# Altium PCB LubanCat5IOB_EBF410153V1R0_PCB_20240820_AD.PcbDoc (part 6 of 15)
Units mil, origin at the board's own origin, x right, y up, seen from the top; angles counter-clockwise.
Board outline 6811.02 x 4055.12 mil, 6 copper layers (TOP, GND02, ART03, ART04, PWR05, BOTTOM), stack 59.279 mil thick; 981 components, 783 nets, 3627 pads, 2669 vias.
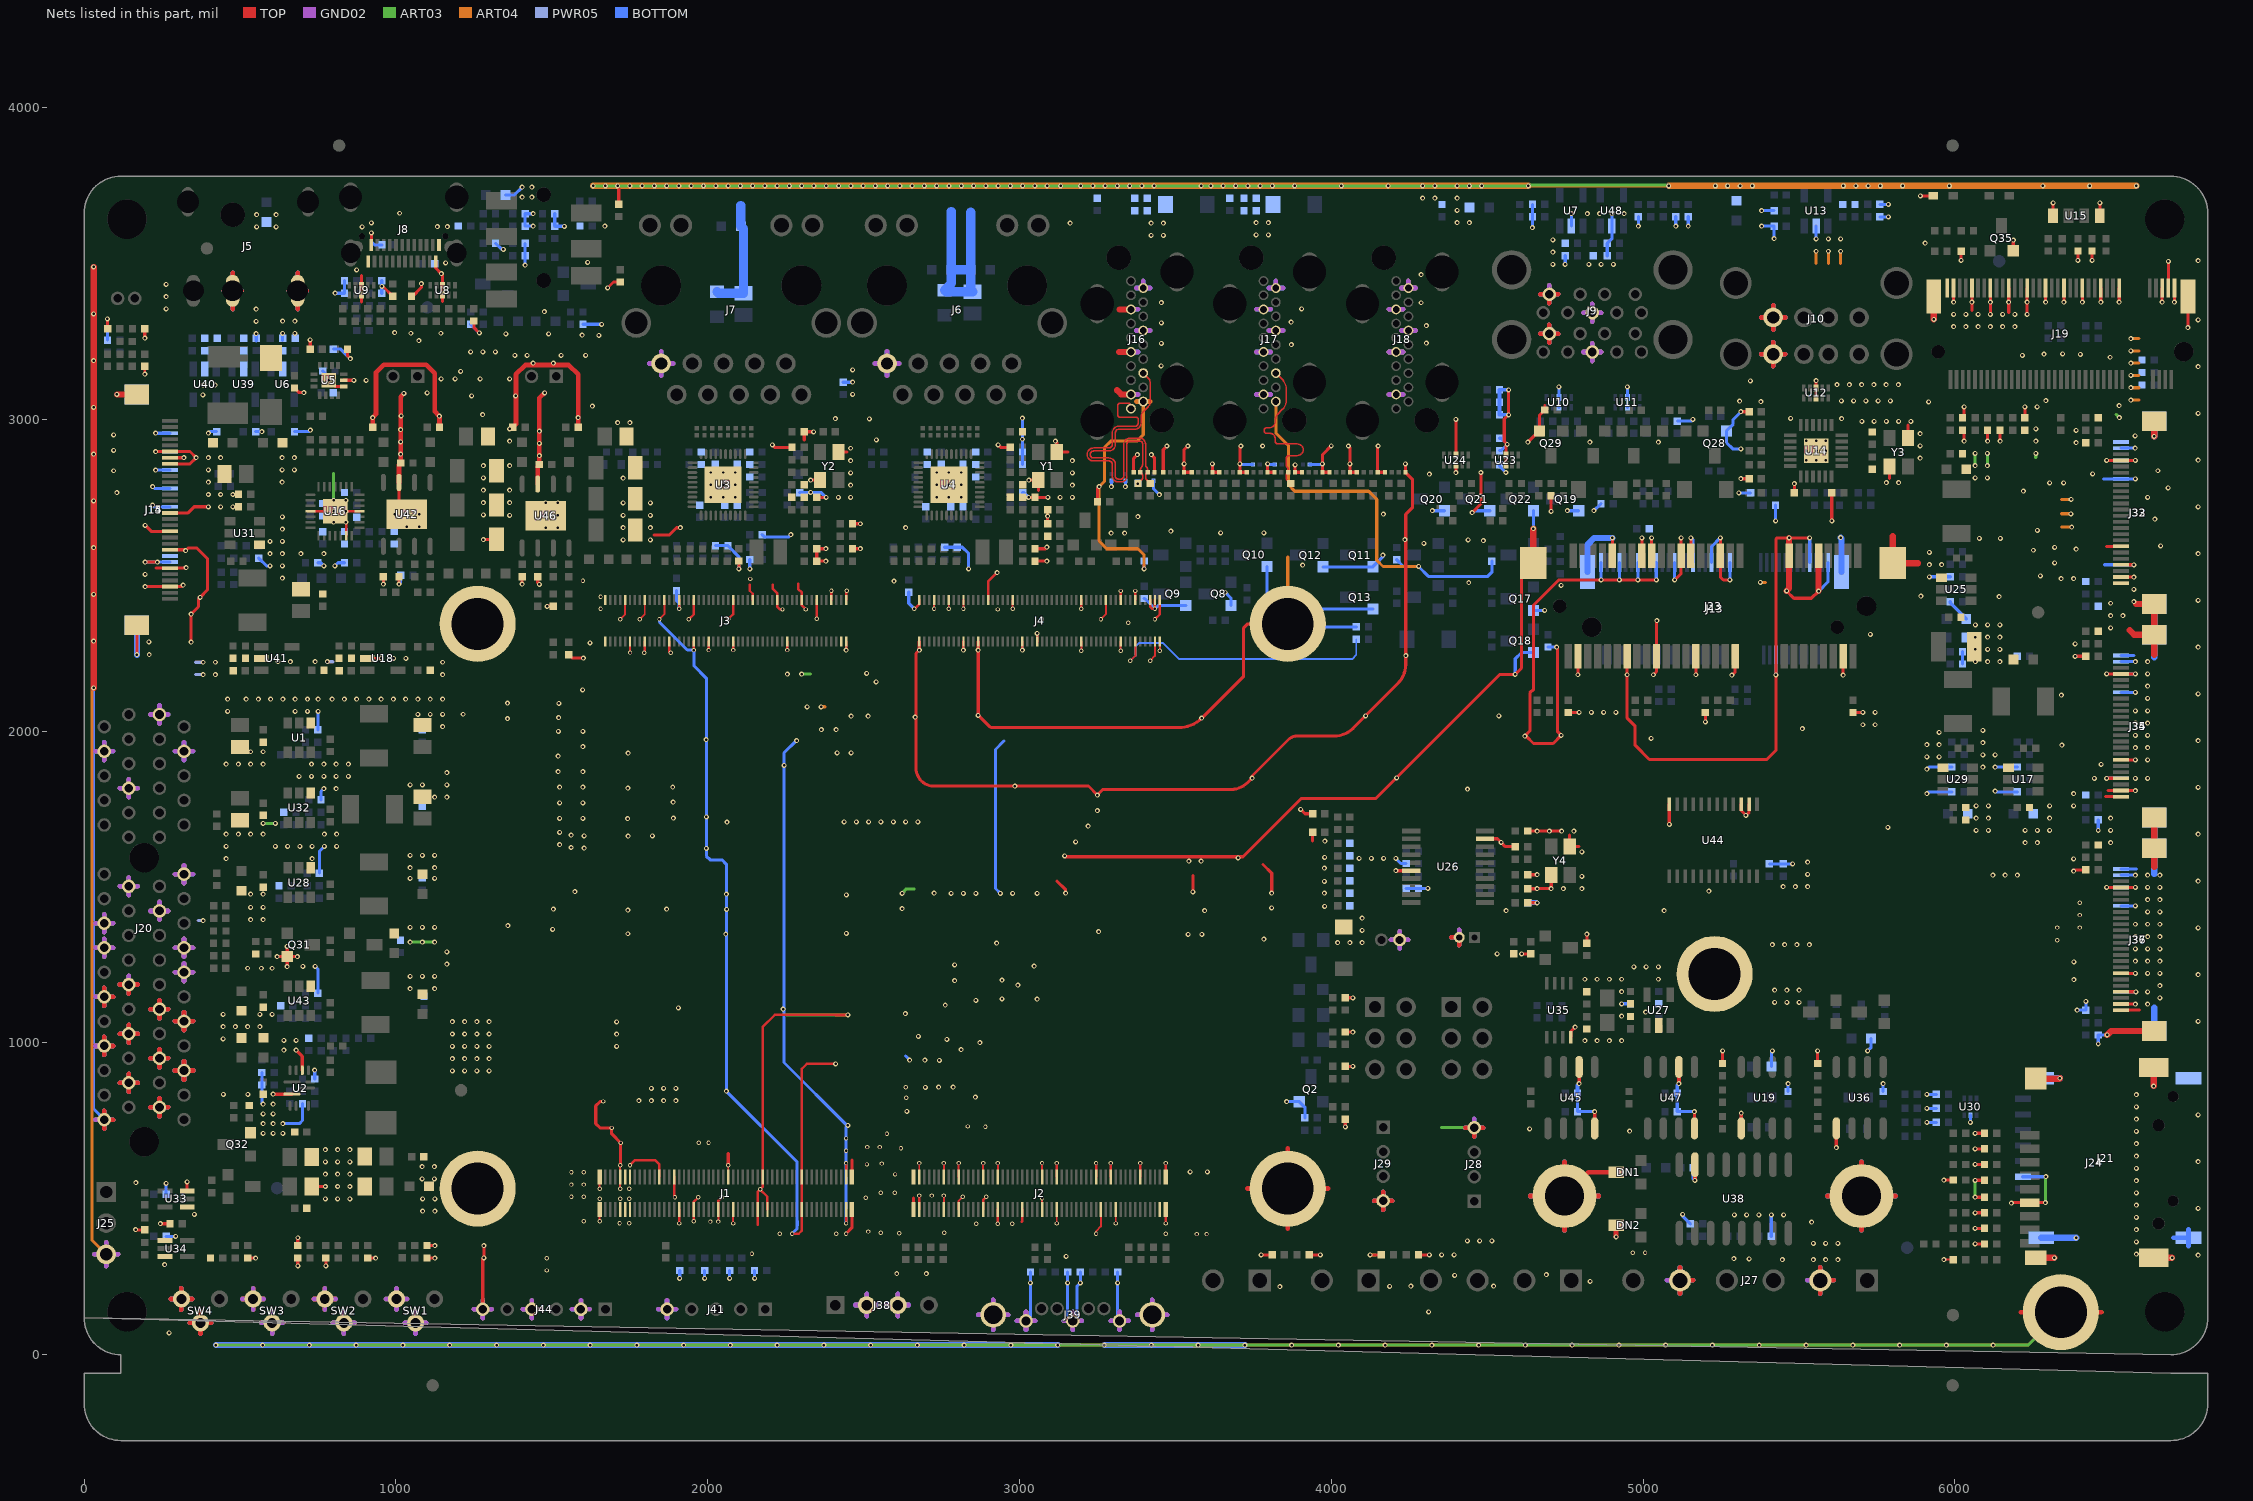
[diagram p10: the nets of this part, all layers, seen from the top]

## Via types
v1: diameter 16, hole 8, TOP to BOTTOM, 2357 vias
v2: diameter 14, hole 8, TOP to BOTTOM, 308 vias
v3: diameter 20, hole 10, TOP to BOTTOM, 4 vias

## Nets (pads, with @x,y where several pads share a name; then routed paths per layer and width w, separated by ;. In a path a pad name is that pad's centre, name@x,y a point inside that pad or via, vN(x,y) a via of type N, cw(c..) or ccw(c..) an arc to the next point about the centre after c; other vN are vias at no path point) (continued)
GND: (continued)
  ART04 w15: 32.36,321.89 J25.3@70.86,321.89 ; 35.91,753.93 J20.B32@64.56,753.93 ; 35.91,990.15 J20.B26@64.56,990.15 ; 35.91,1147.63 J20.B22@64.56,1147.63 ; 35.91,1305.11 J20.B18@64.56,1305.11 ; 35.91,1383.85 J20.B16@64.56,1383.85 ; 64.56,725.28 J20.B32@64.56,753.93 ; 64.56,782.59 J20.B32@64.56,753.93 ; 64.56,961.5 J20.B26@64.56,990.15 ; 64.56,1018.81 J20.B26@64.56,990.15 ; 64.56,1118.98 J20.B22@64.56,1147.63 ; 64.56,1176.29 J20.B22@64.56,1147.63 ; 64.56,1276.46 J20.B18@64.56,1305.11 ; 64.56,1333.77 J20.B18@64.56,1305.11 ; 64.56,1355.2 J20.B16@64.56,1383.85 ; 64.56,1412.51 J20.B16@64.56,1383.85 ; 70.86,283.39 J25.3@70.86,321.89 ; 70.86,360.38 J25.3@70.86,321.89 ; 93.22,753.93 J20.B32@64.56,753.93 ; 93.22,990.15 J20.B26@64.56,990.15 ; 93.22,1147.63 J20.B22@64.56,1147.63 ; 93.22,1305.11 J20.B18@64.56,1305.11 ; 93.22,1383.85 J20.B16@64.56,1383.85 ; 109.36,321.89 J25.3@70.86,321.89 ; 114.65,872.04 J20.B29@143.3,872.04 ; 114.65,1029.52 J20.B25@143.3,1029.52 ; 114.65,1187 J20.B21@143.3,1187 ; 114.65,1501.96 J20.B13@143.3,1501.96 ; 114.65,1816.92 J20.B7@143.3,1816.92 ; 143.3,843.39 J20.B29@143.3,872.04 ; 143.3,900.7 J20.B29@143.3,872.04 ; 143.3,1000.87 J20.B25@143.3,1029.52 ; 143.3,1058.18 J20.B25@143.3,1029.52 ; 143.3,1158.35 J20.B21@143.3,1187 ; 143.3,1215.66 J20.B21@143.3,1187 ; 143.3,1473.31 J20.B13@143.3,1501.96 ; 143.3,1530.62 J20.B13@143.3,1501.96 ; 143.3,1788.27 J20.B7@143.3,1816.92 ; 143.3,1845.58 J20.B7@143.3,1816.92 ; 171.96,872.04 J20.B29@143.3,872.04 ; 171.96,1029.52 J20.B25@143.3,1029.52 ; 171.96,1187 J20.B21@143.3,1187 ; 171.96,1501.96 J20.B13@143.3,1501.96 ; 171.96,1816.92 J20.B7@143.3,1816.92 ; 213.07,793.3 J20.A31@241.73,793.3 ; 213.07,950.78 J20.A27@241.73,950.78 ; 213.07,1108.26 J20.A23@241.73,1108.26 ; 213.07,1423.22 J20.A15@241.73,1423.22 ; 241.73,764.65 J20.A31@241.73,793.3 ; 241.73,821.96 J20.A31@241.73,793.3 ; 241.73,922.13 J20.A27@241.73,950.78 ; 241.73,979.44 J20.A27@241.73,950.78 ; 241.73,1079.61 J20.A23@241.73,1108.26 ; 241.73,1136.92 J20.A23@241.73,1108.26 ; 241.73,1394.57 J20.A15@241.73,1423.22 ; 241.73,1451.88 J20.A15@241.73,1423.22 ; 270.38,793.3 J20.A31@241.73,793.3 ; 270.38,950.78 J20.A27@241.73,950.78 ; 270.38,1108.26 J20.A23@241.73,1108.26 ; 270.38,1423.22 J20.A15@241.73,1423.22 ; 277.53,178.81 SW4.1@312.09,178.81 ; 291.81,911.41 J20.A28@320.47,911.41 ; 291.81,1068.89 J20.A24@320.47,1068.89 ; 291.81,1226.37 J20.A20@320.47,1226.37 ; 291.81,1305.11 J20.A18@320.47,1305.11 ; 291.81,1541.33 J20.A12@320.47,1541.33 ; 312.09,144.25 SW4.1@312.09,178.81 ; 312.09,213.38 SW4.1@312.09,178.81 ; 320.47,882.76 J20.A28@320.47,911.41 ; 320.47,940.07 J20.A28@320.47,911.41 ; 320.47,1040.24 J20.A24@320.47,1068.89 ; 320.47,1097.55 J20.A24@320.47,1068.89 ; 320.47,1197.72 J20.A20@320.47,1226.37 ; 320.47,1255.03 J20.A20@320.47,1226.37 ; 320.47,1276.46 J20.A18@320.47,1305.11 ; 320.47,1333.77 J20.A18@320.47,1305.11 ; 320.47,1512.68 J20.A12@320.47,1541.33 ; 320.47,1569.99 J20.A12@320.47,1541.33 ; 338.55,102.04 SW4.3@373.11,102.04 ; 346.65,178.81 SW4.1@312.09,178.81 ; 349.12,911.41 J20.A28@320.47,911.41 ; 349.12,1068.89 J20.A24@320.47,1068.89 ; 349.12,1226.37 J20.A20@320.47,1226.37 ; 349.12,1305.11 J20.A18@320.47,1305.11 ; 373.11,67.48 SW4.3@373.11,102.04 ; 373.11,136.6 SW4.3@373.11,102.04 ; 407.67,102.04 SW4.3@373.11,102.04 ; 507.53,178.81 SW3.1@542.09,178.81 ; 542.09,144.25 SW3.1@542.09,178.81 ; 542.09,213.38 SW3.1@542.09,178.81 ; 568.55,102.04 SW3.3@603.11,102.04 ; 576.65,178.81 SW3.1@542.09,178.81 ; 603.11,67.48 SW3.3@603.11,102.04 ; 603.11,136.6 SW3.3@603.11,102.04 ; 637.67,102.04 SW3.3@603.11,102.04 ; 737.53,178.81 SW2.1@772.09,178.81 ; 772.09,144.25 SW2.1@772.09,178.81 ; 772.09,213.38 SW2.1@772.09,178.81 ; 798.55,102.04 SW2.3@833.11,102.04 ; 806.65,178.81 SW2.1@772.09,178.81 ; 833.11,67.48 SW2.3@833.11,102.04 ; 833.11,136.6 SW2.3@833.11,102.04 ; 867.67,102.04 SW2.3@833.11,102.04 ; 3751.13,2343.81 SS6.1@3860.49,2343.81 ; 3860.49,2234.45 SS6.1@3860.49,2343.81 ; 3969.85,2343.81 SS6.1@3860.49,2343.81 ; 4137.72,493.42 J29.4@4166.38,493.42 ; 4166.38,464.76 J29.4@4166.38,493.42 ; 4185.36,3079.7 J18.17@4208.11,3079.7 4230.86,3079.7 ; 4185.36,3216.11 J18.11@4208.11,3216.11 4230.86,3216.11 ; 4185.36,3352.53 J18.5@4208.11,3352.53 4230.86,3352.53 ; 4191.86,1330.6 J12.2@4219.53,1330.6 ; 4195.03,493.42 J29.4@4166.38,493.42 ; 4219.53,1358.27 J12.2@4219.53,1330.6 ; 4224.73,3284.53 J18.8@4247.48,3284.53 4270.23,3284.53 ; 4224.73,3421.08 J18.2@4247.48,3421.08 ; 4247.2,1330.6 J12.2@4219.53,1330.6 ; 4247.48,3443.83 J18.2@4247.48,3421.08 ; 4270.23,3421.08 J18.2@4247.48,3421.08 ; 4385.71,1338.42 J26.2@4410.43,1338.42 ; 4410.43,1313.7 J26.2@4410.43,1338.42 ; 4410.43,1363.14 J26.2@4410.43,1338.42 ; 4638.66,509.17 SS9.1@4748.02,509.17 ; 4670.99,3274.86 J9.13@4699.64,3274.86 ; 4670.99,3400.86 J9.4@4699.64,3400.86 ; 4699.64,3246.21 J9.13@4699.64,3274.86 ; 4699.64,3303.52 J9.13@4699.64,3274.86 ; 4699.64,3372.21 J9.4@4699.64,3400.86 ; 4699.64,3429.52 J9.4@4699.64,3400.86 ; 4728.3,3274.86 J9.13@4699.64,3274.86 ; 4728.3,3400.86 J9.4@4699.64,3400.86 ; 4748.02,399.81 SS9.1@4748.02,509.17 ; 4808.78,3215.77 J9.16@4837.44,3215.77 ; 4808.78,3341.77 J9.7@4837.44,3341.77 ; 4837.44,3187.11 J9.16@4837.44,3215.77 ; 4837.44,3244.42 J9.16@4837.44,3215.77 ; 4837.44,3313.11 J9.7@4837.44,3341.77 ; 4837.44,3370.42 J9.7@4837.44,3341.77 ; 4857.38,509.17 SS9.1@4748.02,509.17 ; 4866.1,3215.77 J9.16@4837.44,3215.77 ; 4866.1,3341.77 J9.7@4837.44,3341.77 ; 5378.82,3208.66 J10.4@5417.32,3208.66 ; 5378.82,3326.77 J10.10@5417.32,3326.77 ; 5417.32,3170.16 J10.4@5417.32,3208.66 ; 5417.32,3247.16 J10.4@5417.32,3208.66 ; 5417.32,3288.27 J10.10@5417.32,3326.77 ; 5417.32,3365.27 J10.10@5417.32,3326.77 ; 5455.82,3208.66 J10.4@5417.32,3208.66 ; 5455.82,3326.77 J10.10@5417.32,3326.77
  ART04 w20: v1(1632.28,3748.84) v1(1671.65,3748.84) v1(1711.02,3748.84) v1(1750.39,3748.84) v1(1789.76,3748.84) v1(1829.13,3748.84) v1(1868.5,3748.84) v1(1907.87,3748.84) v1(1947.24,3748.84) v1(1986.61,3748.84) v1(2025.98,3748.84) v1(2065.35,3748.84) v1(2104.72,3748.84) v1(2144.09,3748.84) v1(2183.46,3748.84) v1(2222.83,3748.84) v1(2262.2,3748.84) v1(2301.57,3748.84) v1(2340.94,3748.84) v1(2380.31,3748.84) v1(2419.68,3748.84) v1(2459.05,3748.84) v1(2498.42,3748.84) v1(2537.79,3748.84) v1(2577.16,3748.84) v1(2616.53,3748.84) v1(2655.9,3748.84) v1(2695.27,3748.84) v1(2734.64,3748.84) v1(2774.01,3748.84) v1(2813.38,3748.84) v1(2852.75,3748.84) v1(2892.12,3748.84) v1(2931.49,3748.84) v1(2970.86,3748.84) v1(3010.23,3748.84) v1(3049.6,3748.84) v1(3088.97,3748.84) v1(3132.28,3748.84) v1(3196.06,3748.84) v1(3235.43,3748.84) v1(3274.8,3748.84) v1(3314.17,3748.84) v1(3353.54,3748.84) v1(3392.91,3748.84) v1(3432.28,3748.84) v1(3582.28,3748.84) v1(3614.17,3748.84) v1(3653.54,3748.84) v1(3692.91,3748.84) v1(3732.28,3748.84) v1(3771.65,3748.84) v1(3811.02,3748.84) v1(3882.28,3748.84) v1(4032.28,3748.84) v1(4182.28,3748.84) v1(4292.91,3748.84) v1(4332.28,3748.84) v1(4403.54,3748.84) v1(4442.91,3748.84) v1(4482.28,3748.84) v1(4632.28,3748.84) ; v1(5082.28,3748.84) v1(5232.28,3748.84) v1(5271.65,3748.84) v1(5311.02,3748.84) v1(5350.39,3748.84) v1(5642.91,3748.84) v1(5682.28,3748.84) v1(5721.65,3748.84) v1(5761.02,3748.84) v1(5832.28,3748.84) v1(5982.28,3748.84) v1(6282.28,3748.84) v1(6432.28,3748.84) v1(6582.28,3748.84)
  PWR05 w10: 357.79,2181.42 v1(381.57,2181.42) ; 357.79,2220.79 v1(381.57,2220.79) ; 365.63,1392.37 v1(382,1392.37) ; v1(780,2222.52) 797.52,2222.52
  PWR05 w15: 32.36,321.89 J25.3@70.86,321.89 ; 35.91,753.93 J20.B32@64.56,753.93 ; 35.91,990.15 J20.B26@64.56,990.15 ; 35.91,1147.63 J20.B22@64.56,1147.63 ; 35.91,1305.11 J20.B18@64.56,1305.11 ; 35.91,1383.85 J20.B16@64.56,1383.85 ; 35.91,1935.04 J20.B4@64.56,1935.04 ; 64.56,725.28 J20.B32@64.56,753.93 ; 64.56,782.59 J20.B32@64.56,753.93 ; 64.56,961.5 J20.B26@64.56,990.15 ; 64.56,1018.81 J20.B26@64.56,990.15 ; 64.56,1118.98 J20.B22@64.56,1147.63 ; 64.56,1176.29 J20.B22@64.56,1147.63 ; 64.56,1276.46 J20.B18@64.56,1305.11 ; 64.56,1333.77 J20.B18@64.56,1305.11 ; 64.56,1355.2 J20.B16@64.56,1383.85 ; 64.56,1412.51 J20.B16@64.56,1383.85 ; 64.56,1906.38 J20.B4@64.56,1935.04 ; 64.56,1963.69 J20.B4@64.56,1935.04 ; 70.86,283.39 J25.3@70.86,321.89 ; 70.86,360.38 J25.3@70.86,321.89 ; 93.22,753.93 J20.B32@64.56,753.93 ; 93.22,990.15 J20.B26@64.56,990.15 ; 93.22,1147.63 J20.B22@64.56,1147.63 ; 93.22,1305.11 J20.B18@64.56,1305.11 ; 93.22,1383.85 J20.B16@64.56,1383.85 ; 93.22,1935.04 J20.B4@64.56,1935.04 ; 109.36,321.89 J25.3@70.86,321.89 ; 114.65,872.04 J20.B29@143.3,872.04 ; 114.65,1029.52 J20.B25@143.3,1029.52 ; 114.65,1187 J20.B21@143.3,1187 ; 114.65,1501.96 J20.B13@143.3,1501.96 ; 114.65,1816.92 J20.B7@143.3,1816.92 ; 143.3,843.39 J20.B29@143.3,872.04 ; 143.3,900.7 J20.B29@143.3,872.04 ; 143.3,1000.87 J20.B25@143.3,1029.52 ; 143.3,1058.18 J20.B25@143.3,1029.52 ; 143.3,1158.35 J20.B21@143.3,1187 ; 143.3,1215.66 J20.B21@143.3,1187 ; 143.3,1473.31 J20.B13@143.3,1501.96 ; 143.3,1530.62 J20.B13@143.3,1501.96 ; 143.3,1788.27 J20.B7@143.3,1816.92 ; 143.3,1845.58 J20.B7@143.3,1816.92 ; 171.96,872.04 J20.B29@143.3,872.04 ; 171.96,1029.52 J20.B25@143.3,1029.52 ; 171.96,1187 J20.B21@143.3,1187 ; 171.96,1501.96 J20.B13@143.3,1501.96 ; 171.96,1816.92 J20.B7@143.3,1816.92 ; 213.07,793.3 J20.A31@241.73,793.3 ; 213.07,950.78 J20.A27@241.73,950.78 ; 213.07,1108.26 J20.A23@241.73,1108.26 ; 213.07,1423.22 J20.A15@241.73,1423.22 ; 213.07,2053.14 J20.A1@241.73,2053.14 ; 241.73,764.65 J20.A31@241.73,793.3 ; 241.73,821.96 J20.A31@241.73,793.3 ; 241.73,922.13 J20.A27@241.73,950.78 ; 241.73,979.44 J20.A27@241.73,950.78 ; 241.73,1079.61 J20.A23@241.73,1108.26 ; 241.73,1136.92 J20.A23@241.73,1108.26 ; 241.73,1394.57 J20.A15@241.73,1423.22 ; 241.73,1451.88 J20.A15@241.73,1423.22 ; 241.73,2024.49 J20.A1@241.73,2053.14 ; 241.73,2081.8 J20.A1@241.73,2053.14 ; 270.38,793.3 J20.A31@241.73,793.3 ; 270.38,950.78 J20.A27@241.73,950.78 ; 270.38,1108.26 J20.A23@241.73,1108.26 ; 270.38,1423.22 J20.A15@241.73,1423.22 ; 270.38,2053.14 J20.A1@241.73,2053.14 ; 277.53,178.81 SW4.1@312.09,178.81 ; 291.81,911.41 J20.A28@320.47,911.41 ; 291.81,1068.89 J20.A24@320.47,1068.89 ; 291.81,1226.37 J20.A20@320.47,1226.37 ; 291.81,1305.11 J20.A18@320.47,1305.11 ; 291.81,1541.33 J20.A12@320.47,1541.33 ; 291.81,1935.04 J20.A4@320.47,1935.04 ; 312.09,144.25 SW4.1@312.09,178.81 ; 312.09,213.38 SW4.1@312.09,178.81 ; 320.47,882.76 J20.A28@320.47,911.41 ; 320.47,940.07 J20.A28@320.47,911.41 ; 320.47,1040.24 J20.A24@320.47,1068.89 ; 320.47,1097.55 J20.A24@320.47,1068.89 ; 320.47,1197.72 J20.A20@320.47,1226.37 ; 320.47,1255.03 J20.A20@320.47,1226.37 ; 320.47,1276.46 J20.A18@320.47,1305.11 ; 320.47,1333.77 J20.A18@320.47,1305.11 ; 320.47,1512.68 J20.A12@320.47,1541.33 ; 320.47,1569.99 J20.A12@320.47,1541.33 ; 320.47,1906.38 J20.A4@320.47,1935.04 ; 320.47,1963.69 J20.A4@320.47,1935.04 ; 338.55,102.04 SW4.3@373.11,102.04 ; 346.65,178.81 SW4.1@312.09,178.81 ; 349.12,911.41 J20.A28@320.47,911.41 ; 349.12,1068.89 J20.A24@320.47,1068.89 ; 349.12,1226.37 J20.A20@320.47,1226.37 ; 349.12,1305.11 J20.A18@320.47,1305.11 ; 349.12,1541.33 J20.A12@320.47,1541.33 ; 349.12,1935.04 J20.A4@320.47,1935.04 ; 373.11,67.48 SW4.3@373.11,102.04 ; 373.11,136.6 SW4.3@373.11,102.04 ; 407.67,102.04 SW4.3@373.11,102.04 ; 447.72,3412.17 J5.2@476.37,3412.17 ; 476.37,3353.97 J5.2@476.37,3412.17 ; 476.37,3470.37 J5.2@476.37,3412.17 ; 505.02,3412.17 J5.2@476.37,3412.17 ; 568.55,102.04 SW3.3@603.11,102.04 ; 603.11,67.48 SW3.3@603.11,102.04 ; 603.11,136.6 SW3.3@603.11,102.04 ; 637.67,102.04 SW3.3@603.11,102.04 ; 656.32,3412.17 J5.3@684.97,3412.17 ; 684.97,3353.97 J5.3@684.97,3412.17 ; 684.97,3470.37 J5.3@684.97,3412.17 ; 713.62,3412.17 J5.3@684.97,3412.17 ; 798.55,102.04 SW2.3@833.11,102.04 ; 833.11,67.48 SW2.3@833.11,102.04 ; 833.11,136.6 SW2.3@833.11,102.04 ; 867.67,102.04 SW2.3@833.11,102.04 ; 1028.55,102.04 SW1.3@1063.11,102.04 ; 1063.11,67.48 SW1.3@1063.11,102.04 ; 1063.11,136.6 SW1.3@1063.11,102.04 ; 1097.67,102.04 SW1.3@1063.11,102.04 ; 1152.7,532.79 SS7.1@1262.06,532.79 ; 1152.7,2343.81 SS5.1@1262.06,2343.81 ; 1249.89,145.66 J44.6@1278.54,145.66 ; 1262.06,423.43 SS7.1@1262.06,532.79 ; 1262.06,642.15 SS7.1@1262.06,532.79 ; 1262.06,2234.45 SS5.1@1262.06,2343.81 ; 1262.06,2453.17 SS5.1@1262.06,2343.81 ; 1278.54,117.01 J44.6@1278.54,145.66 ; 1307.2,145.66 J44.6@1278.54,145.66 ; 1371.42,532.79 SS7.1@1262.06,532.79 ; 1371.42,2343.81 SS5.1@1262.06,2343.81 ; 1407.37,145.66 J44.4@1436.02,145.66 ; 1436.02,117.01 J44.4@1436.02,145.66 ; 1464.68,145.66 J44.4@1436.02,145.66 ; 1564.85,145.66 J44.2@1593.5,145.66 1593.5,117.01 ; 1812.29,3179.14 J7.10@1850.79,3179.14 ; 1841.07,145.66 J41.5@1869.72,145.66 ; 1850.79,3140.64 J7.10@1850.79,3179.14 ; 1850.79,3217.64 J7.10@1850.79,3179.14 ; 1869.72,117.01 J41.5@1869.72,145.66 ; 1869.72,174.32 J41.5@1869.72,145.66 ; 1889.29,3179.14 J7.10@1850.79,3179.14 ; 1898.38,145.66 J41.5@1869.72,145.66 ; 2474.17,159.06 J38.2@2509.72,159.06 ; 2509.72,123.51 J38.2@2509.72,159.06 ; 2509.72,194.6 J38.2@2509.72,159.06 ; 2536.7,3179.14 J6.10@2575.2,3179.14 ; 2545.27,159.06 J38.2@2509.72,159.06 ; 2574.17,159.06 J38.3@2609.72,159.06 ; 2575.2,3140.64 J6.10@2575.2,3179.14 ; 2575.2,3217.64 J6.10@2575.2,3179.14 ; 2609.72,123.51 J38.3@2609.72,159.06 ; 2609.72,194.6 J38.3@2609.72,159.06 ; 2613.7,3179.14 J6.10@2575.2,3179.14 ; 2645.27,159.06 J38.3@2609.72,159.06 ; 2867.52,127.95 J39.S1@2915.86,127.95 ; 2915.86,79.61 J39.S1@2915.86,127.95 ; 2915.86,176.29 J39.S1@2915.86,127.95 ; 2964.2,127.95 J39.S1@2915.86,127.95 ; 2992.32,108.27 J39.7@3020.98,108.27 ; 3020.98,79.61 J39.7@3020.98,108.27 ; 3020.98,136.92 J39.7@3020.98,108.27 ; 3049.64,108.27 J39.7@3020.98,108.27 ; 3142.32,108.27 J39.4@3170.98,108.27 ; 3170.98,79.61 J39.4@3170.98,108.27 ; 3170.98,136.92 J39.4@3170.98,108.27 ; 3199.64,108.27 J39.4@3170.98,108.27 ; 3292.32,108.27 J39.1@3320.98,108.27 ; 3320.98,79.61 J39.1@3320.98,108.27 ; 3320.98,136.92 J39.1@3320.98,108.27 ; 3334.97,3079.7 J16.17@3357.72,3079.7 3380.47,3079.7 ; 3334.97,3216.11 J16.11@3357.72,3216.11 3380.47,3216.11 ; 3334.97,3352.53 J16.5@3357.72,3352.53 3380.47,3352.53 ; 3349.64,108.27 J39.1@3320.98,108.27 ; 3374.34,3284.53 J16.8@3397.09,3284.53 3419.84,3284.53 ; 3374.34,3421.08 J16.2@3397.09,3421.08 ; 3377.76,127.95 J39.S2@3426.1,127.95 ; 3397.09,3443.83 J16.2@3397.09,3421.08 ; 3419.84,3421.08 J16.2@3397.09,3421.08 ; 3426.1,79.61 J39.S2@3426.1,127.95 ; 3426.1,176.29 J39.S2@3426.1,127.95 ; 3474.44,127.95 J39.S2@3426.1,127.95 ; 3751.13,532.79 SS8.1@3860.49,532.79 ; 3751.13,2343.81 SS6.1@3860.49,2343.81 ; 3760.16,3079.7 J17.17@3782.91,3079.7 3805.66,3079.7 ; 3760.16,3216.11 J17.11@3782.91,3216.11 3805.66,3216.11 ; 3760.16,3352.53 J17.5@3782.91,3352.53 3805.66,3352.53 ; 3799.53,3284.53 J17.8@3822.28,3284.53 3845.03,3284.53 ; 3799.53,3421.08 J17.2@3822.28,3421.08 ; 3822.28,3443.83 J17.2@3822.28,3421.08 ; 3845.03,3421.08 J17.2@3822.28,3421.08 ; 3860.49,423.43 SS8.1@3860.49,532.79 ; 3860.49,642.15 SS8.1@3860.49,532.79 ; 3860.49,2234.45 SS6.1@3860.49,2343.81 ; 3860.49,2453.17 SS6.1@3860.49,2343.81 ; 3969.85,532.79 SS8.1@3860.49,532.79 ; 3969.85,2343.81 SS6.1@3860.49,2343.81 ; 4137.72,493.42 J29.4@4166.38,493.42 ; 4166.38,464.76 J29.4@4166.38,493.42 ; 4166.38,522.08 J29.4@4166.38,493.42 ; 4185.36,3079.7 J18.17@4208.11,3079.7 4230.86,3079.7 ; 4185.36,3216.11 J18.11@4208.11,3216.11 4230.86,3216.11 ; 4185.36,3352.53 J18.5@4208.11,3352.53 4230.86,3352.53 ; 4191.86,1330.6 J12.2@4219.53,1330.6 ; 4195.03,493.42 J29.4@4166.38,493.42 ; 4219.53,1302.92 J12.2@4219.53,1330.6 ; 4219.53,1358.27 J12.2@4219.53,1330.6 ; 4224.73,3284.53 J18.8@4247.48,3284.53 4270.23,3284.53 ; 4224.73,3421.08 J18.2@4247.48,3421.08 ; 4247.2,1330.6 J12.2@4219.53,1330.6 ; 4247.48,3443.83 J18.2@4247.48,3421.08 ; 4270.23,3421.08 J18.2@4247.48,3421.08 ; 4385.71,1338.42 J26.2@4410.43,1338.42 ; 4410.43,1313.7 J26.2@4410.43,1338.42 ; 4410.43,1363.14 J26.2@4410.43,1338.42 ; 4429.97,728.11 J28.4@4458.62,728.11 ; 4458.62,699.45 J28.4@4458.62,728.11 ; 4458.62,756.77 J28.4@4458.62,728.11 ; 4487.28,728.11 J28.4@4458.62,728.11 ; 4638.66,509.17 SS9.1@4748.02,509.17 ; 4670.99,3274.86 J9.13@4699.64,3274.86 ; 4670.99,3400.86 J9.4@4699.64,3400.86 ; 4699.64,3246.21 J9.13@4699.64,3274.86 ; 4699.64,3303.52 J9.13@4699.64,3274.86 ; 4699.64,3372.21 J9.4@4699.64,3400.86 ; 4699.64,3429.52 J9.4@4699.64,3400.86 ; 4728.3,3274.86 J9.13@4699.64,3274.86 ; 4728.3,3400.86 J9.4@4699.64,3400.86 ; 4748.02,399.81 SS9.1@4748.02,509.17 ; 4748.02,618.53 SS9.1@4748.02,509.17 ; 4808.78,3215.77 J9.16@4837.44,3215.77 ; 4808.78,3341.77 J9.7@4837.44,3341.77 ; 4837.44,3187.11 J9.16@4837.44,3215.77 ; 4837.44,3244.42 J9.16@4837.44,3215.77 ; 4837.44,3313.11 J9.7@4837.44,3341.77 ; 4837.44,3370.42 J9.7@4837.44,3341.77 ; 4857.38,509.17 SS9.1@4748.02,509.17 ; 4866.1,3215.77 J9.16@4837.44,3215.77 ; 4866.1,3341.77 J9.7@4837.44,3341.77 ; 5076.3,238.19 J27.5@5118.74,238.19 ; 5118.74,195.75 J27.5@5118.74,238.19 ; 5118.74,280.62 J27.5@5118.74,238.19 ; 5120.05,1220.89 SS12.1@5229.41,1220.89 ; 5161.17,238.19 J27.5@5118.74,238.19 ; 5229.41,1111.52 SS12.1@5229.41,1220.89 ; 5229.41,1330.25 SS12.1@5229.41,1220.89 ; 5338.77,1220.89 SS12.1@5229.41,1220.89 ; 5378.82,3208.66 J10.4@5417.32,3208.66 ; 5378.82,3326.77 J10.10@5417.32,3326.77 ; 5417.32,3170.16 J10.4@5417.32,3208.66 ; 5417.32,3247.16 J10.4@5417.32,3208.66 ; 5417.32,3288.27 J10.10@5417.32,3326.77 ; 5417.32,3365.27 J10.10@5417.32,3326.77 ; 5455.82,3208.66 J10.4@5417.32,3208.66 ; 5455.82,3326.77 J10.10@5417.32,3326.77 ; 5526.3,238.19 J27.2@5568.74,238.19 ; 5568.74,195.75 J27.2@5568.74,238.19 ; 5568.74,280.62 J27.2@5568.74,238.19 ; 5591.42,509.17 SS10.1@5700.78,509.17 ; 5611.17,238.19 J27.2@5568.74,238.19 ; 5700.78,399.81 SS10.1@5700.78,509.17 ; 5700.78,618.53 SS10.1@5700.78,509.17 ; 5810.14,509.17 SS10.1@5700.78,509.17 ; 6230.88,136.22 SS11.1@6340.24,136.22 ; 6340.24,245.58 SS11.1@6340.24,136.22 ; 6449.6,136.22 SS11.1@6340.24,136.22
  BOTTOM w10: v1(30.68,2138.49) 30.68,787.81 J20.B32@64.56,753.93 ; C125.2@75,3254.05 v1(75,3322) ; v1(195.63,2542.06) v1(235,2542.06) J15.7@275.91,2542.06 ; v1(220,2724.37) 225.14,2719.23 J15.16@275.91,2719.23 ; v1(220,2784.37) 226.09,2778.28 J15.19@275.91,2778.28 ; v1(229.08,2837.34) J15.22@275.91,2837.34 ; v1(229.08,2896.39) J15.25@275.91,2896.39 ; v1(229.08,2955.45) J15.28@275.91,2955.45 ; v1@258.14,288.94 v1(258.54,288.54) ; D55.2@263.1,379.37 v1(293.37,379.37) ; D56.2@263.1,514.37 v1(263.1,549) ; v1(398.74,2955.65) 403.41,2960.32 C262.2@425,2960.32 ; C259.2@550,2960.32 v1(570,2960.32) ; R308.2@552,3252.05 R308.2@552,3260.05 v1(552,3275) ; R271.2@560,2554.69 584.89,2529.8 v1(596.26,2529.8) ; R16.2@570.32,905.04 C26.2@570.32,865.04 570.32,808.04 v1(574.5,803.87) ; C87.2@636.68,3252.37 C87.2@636.68,3260.37 v1(636.68,3275.32) ; v1(637.48,740.88) 690.32,740.88 700.32,750.89 R18.2@700.32,805.04 ; C86.2@675,2960.32 720.95,2960.32 v1(725.63,2965) ; C25.2@739.68,884.37 v1(739.68,913) ; v1(741.26,1245.32) 749.68,1236.9 R322.2@749.68,1159.37 ; R7.2@749.68,2004.37 749.68,2057.09 750.9,2058.31 v1(750.9,2063.31) ; C123.2@749.68,2540 759.17,2540 v1(769.37,2529.8) ; R250.2@754.68,1544.37 754.68,1613.97 v1(770.71,1630) ; R274.2@759.68,1779.37 759.68,1806.57 v1(768.74,1815.63) ; C78.2@765.32,3155 785,3135.32 v1(785,3125) ; C77.2@799.68,3225 823.43,3225 v1(853.9,3194.53) ; v1(804.37,2529.8) 814.57,2540 C124.2@835.32,2540 ; v1(805,3404.37) R98.2@835.32,3404.37 D13.1@835.32,3444.37 ; v1(921.26,3598.19) 921.26,3569.37 931.26,3559.37 D11.1@955.32,3559.37 ; R97.2@954.68,3404.37 v1@954.68,3426.32 ; D12.1@954.68,3444.37 v1@954.68,3426.32 ; v1(955,3426) v1@954.68,3426.32 ; v1(1010,2471) 1015.32,2476.32 C299.1@1015.32,2500 ; R325.2@1240,3304.69 v1(1267.85,3276.84) ; R327.2@1319.68,3564.37 1339,3545.05 v1(1345,3545.05) ; L12.2@1351.5,3719.37 1380,3719.37 v1(1405,3744.37) ; v1(1414.68,3494.37) C289.2@1414.68,3524.37 C111.2@1414.68,3564.37 ; v1(1440,3619.37) C121.2@1414.68,3619.37 R118.2@1414.68,3659.37 v1(1440,3659.37) ; C116.2@1509.68,3659.37 1509.68,3619.37 R117.1@1510,3619.05 v1(1540.32,3619.05) ; R123.2@1600,3304.69 v1(1660,3304.69) ; v2(1845.38,2359) 1845.38,2349.62 1935,2260 v2(1955.62,2260) 1955.62,2210.38 1996,2170 v1(1996,1725) v1(1996,1624) 1996,1599 2008,1587 2046,1587 2060,1573 v1(2060,1477) v1(2060,845) 2286.32,618.68 2286.32,428.62 2287.17,427.76 2287.17,414.01 2286.32,413.16 2286.32,403.63 v2(2270.57,387.89) ; R58.2@1900,2450.32 1900,2418.18 1908.37,2409.81 v2(1908.37,2392) ; v1(1910.32,245) D48.2@1910.32,270 ; v1(1990.32,245) D47.2@1990.32,270 ; R60.2@2025,2594.68 R59.2@2065,2594.68 2100,2559.68 v1(2100,2520) ; v1(2070.32,245) D25.2@2070.32,270 ; v1(2135,2520) C71.2@2135,2550.32 ; v1(2150.32,245) D24.2@2150.32,270 ; C70.2@2174.68,2630 2181.68,2623 2260,2623 v1(2267,2630) ; v1(2285,1969.37) 2284.37,1969.37 2245,1930 v1(2245,1890) 2245,937 2446.33,735.67 v1(2450,735.67) 2443.8,729.47 v2(2443.8,420.89) ; R68.2@2295,2764.68 2364.68,2764.68 v1(2379.68,2749.68) ; 2635,958 v1(2648,945) ; R30.2@2645,2445.32 2645,2410 v2(2663,2392) ; R32.2@2760,2589.68 R31.2@2800,2589.68 2816.99,2589.68 2836.99,2569.68 v1(2836.99,2520) ; v1(2938.59,1479.74) 2923,1495.33 2923,1941 2950,1968 ; R43.2@3009.68,2855 C35.2@3009.68,2895 v1(3009.68,2936) v1(3009.68,3004) ; R38.2@3010,2764.68 3014.68,2764.68 v1(3029.68,2749.68) ; J39.7@3020.98,108.27 3035.32,122.61 v1(3035.32,230) D85.1@3035.32,265 ; D86.1@3154.68,265 v1(3154.68,230) 3154.68,124.57 J39.4@3170.98,108.27 3185,122.29 3185,220 v1(3195,230) 3195.32,230.32 D87.1@3195.32,265 ; v1(3295,2784.37) D31.1@3295,2802.9 ; D88.1@3314.68,265 v1(3314.68,230) 3314.68,114.57 J39.1@3320.98,108.27 ; v1(3340,2784.37) D29.1@3340,2802.9 ; R160.2@3400,2425.32 3401.34,2425.32 v2(3434.66,2392) 3445.16,2402.5 Q9.2@3533.5,2402.5 ; D28.1@3430,2802.9 3430,2777.37 v1(3449,2758.37) ; v1(3660,2445) 3678.5,2426.5 Q8.2@3678.5,2402.5 ; v1(3706.83,2857) 3708.83,2855 D38.1@3749.17,2855 ; Q10.2@3793.5,2527.5 3793.5,2410.8 SS6.1@3860.49,2343.81 ; v1(3795.83,2857) 3797.83,2855 D36.1@3819.17,2855 ; v1(3856.5,811.5) Q2.2@3897.5,811.5 3915.32,793.68 R135.2@3915.32,760 ; D35.1@3930.83,2855 3969.83,2855 v1(3971.83,2857) ; Q12.2@3973.5,2526.87 Q11.2@4133.5,2526.87 4165.45,2558.82 v1(4165.45,2564.37) ; R171.2@4080.32,2334.37 3869.93,2334.37 SS6.1@3860.49,2343.81 ; Q13.2@4133.5,2391.87 3908.55,2391.87 SS6.1@3860.49,2343.81 ; v1(4207.2,1591.58) 4223.46,1575.32 C168.2@4240,1575.32 ; C166.2@4240,1495.32 C167.2@4280,1495.32 v1(4310,1495.32) ; v1(4324.2,2706.87) Q20.2@4363.5,2706.87 ; v1(4452,2700.37) 4453.37,2700.37 4459.87,2706.87 Q21.2@4508.5,2706.87 ; D44.1@4539.68,2854.37 4539.68,2849.69 v1(4560,2829.37) ; D43.1@4539.68,2899.37 4544.48,2899.37 v1(4564.48,2919.37) 4544.48,2939.37 D41.1@4539.68,2939.37 ; v1(4590,2182) 4590,2231.87 4610,2251.87 Q18.2@4648.5,2251.87 ; v1(4645.32,3614.69) R99.2@4645.32,3649.37 C89.2@4645.32,3689.37 ; Q17.2@4648.5,2386.87 v1(4684.23,2386.87) ; v1(4648.5,2649.37) Q22.2@4648.5,2706.87 ; R181.2@4695,2269.69 v1(4722.68,2269.68) ; U10.8@4730,3038.62 U10.3@4730,3070.12 v1(4730,3104.37) ; v1(4750.32,3497.05) C91.2@4750.32,3524.37 ; v1(4757.5,2706.87) Q19.2@4793.5,2706.87 ; U7.2@4770,3620.16 v1(4770,3659.37) ; C217.2@4789.68,839.37 C216.2@4789.68,779.37 v1(4845,779.37) ; v1(4842.34,2707.03) R192.2@4865,2729.69 ; v1(4865.24,2484.61) J13.75@4865.24,2540.77 ; C286.2@4885.32,3524.37 C285.2@4885.32,3564.37 4900,3579.05 U48.2@4900,3620.16 v1(4900,3659.37) ; v1(4924.29,2484.61) J13.69@4924.29,2540.77 ; v1(4931.32,1125.32) C186.2@4960,1125.32 ; U11.8@4950,3038.62 U11.3@4950,3070.12 v1(4950,3104.37) ; v1(4983.35,2484.61) J13.63@4983.35,2540.77 ; v1(4985,3619.37) C284.2@4985,3649.69 ; v1(5042.4,2484.61) J13.57@5042.4,2540.77 ; v1(5101.46,2484.61) J13.51@5101.46,2540.77 ; v1(5105,3619.37) R149.2@5105,3649.69 ; R211.2@5110,2994.05 5154.68,2994.05 v1(5160,2999.37) ; v1(5115,869.37) 5109.68,864.05 C314.2@5109.68,839.37 C313.2@5109.68,779.37 v1(5165,779.37) ; v1(5127,449.57) 5127,444.26 C245.2@5151.9,419.37 ; v1(5145,3619.37) C253.2@5145,3649.69 ; v1(5153.55,2619.63) 5160.51,2612.66 J13.45@5160.51,2540.77 ; J13.39@5219.57,2540.77 5219.57,2591.17 v1(5248.03,2619.63) ; v1(5278.62,2484.61) J13.33@5278.62,2540.77 ; v1(5307.32,2764.05) C93.2@5345,2764.05 ; v1(5314,2905) 5287.5,2905 5267.5,2925 Q28.2@5267.5,2962.87 5289,2984.37 5289,2999.37 v1(5314,3024.37) ; v1(5380.32,3619.37) R103.2@5420.32,3619.37 v1(5420.32,3579.37) ; v1(5380.32,3669.37) C99.2@5420.32,3669.37 ; C212.2@5405,1574.05 C213.2@5450,1574.05 v1(5479.69,1574.05) ; C246.2@5411.26,379.37 v1(5411.26,448.05) ; R295.2@5411.5,924.37 5411.5,970.87 v1(5415,974.37) ; v1(5425,2674.37) C94.2@5425,2724.69 ; v1(5426.26,2180.11) J13.18@5426.26,2243.52 ; C243.2@5465,844.05 v1(5465,869.37) ; J13.7@5534.53,2540.77 v1(5534.53,2619.37) ; v1(5555,3578.37) U13.2@5555,3620.16 ; v1(5562.99,2449) 5593.58,2479.59 J13.1@5593.58,2540.77 ; v1(5720,974.37) 5731.5,985.87 R289.2@5731.5,1014.37 ; C92.2@5759.68,3649.37 v1(5787,3649.37) ; C97.2@5759.68,3689.37 v1(5787,3689.37) ; C242.2@5770,844.05 v1(5770,869.37) ; v1(5910,745) C207.2@5940.32,745 ; v1(5910,790) C208.2@5940.32,790 ; v1(5910,835) C209.2@5940.32,835 ; v1(5910.63,1799.37) 5916.26,1805 R263.2@5990.32,1805 ; v1(5910.63,1878.11) 5917.52,1885 R261.2@5990.32,1885 ; v1(5918,2494.37) 5918.63,2495 R227.2@5985.32,2495 ; R222.2@5985.32,2415 5985.32,2411.18 C160.2@6036.5,2360 ; C203.2@6024.68,2215 C202.2@6024.68,2255 ; v1(6050,745) U30.2@6050,768.42 ; v1(6128.97,1807.6) 6131.57,1805 R139.2@6200.32,1805 ; v1(6128.97,1884.37) 6129.6,1885 R141.2@6200.32,1885 ; v1(6392,1105) C277.2@6420.32,1105 v1(6420.32,1133.32) ; v1(6460,997) C276.2@6460,1025.32 v1(6488.32,1025.32) ; v1(6460,1681.26) C272.2@6460,1715.32 ; 6476.39,2808.98 J33.18@6533.11,2808.98 v1(6579.25,2808.98) ; v1(6486.97,1848.66) J35.4@6533.11,1848.66 ; J37.4@6533.11,1163.94 v1(6580.35,1163.94) ; J37.18@6533.11,1439.53 v1(6579.25,1439.53) ; J37.21@6533.11,1498.58 v1(6579.25,1498.58) ; J37.23@6533.11,1537.95 v1(6579.25,1537.95) ; J37.24@6533.11,1557.64 6582.73,1557.64 ; J35.18@6533.11,2124.25 v1(6579.25,2124.25) ; J35.21@6533.11,2183.31 v1(6579.25,2183.31) ; J35.23@6533.11,2222.68 v1(6578.7,2222.68) ; J35.24@6533.11,2242.36 6573.99,2242.36 ; J33.21@6533.11,2868.03 v1(6579.25,2868.03) ; J33.23@6533.11,2907.4 v1(6578.62,2907.4)
  BOTTOM w12: C56.2@2435,3119.05 v1(2464.68,3119.05) ; v1(4568.53,3014.37) C155.2@4539.68,3014.37 D45.1@4539.68,3054.37 D42.1@4539.68,3094.37 v1(4568.53,3094.37) ; C217.2@4789.68,839.37 4789.68,864.05 v1(4795,869.37) ; C244.2@5161.26,599.37 5161.26,564.09 v1(5166.37,558.97) ; J21.5@6218.9,570.79 v1(6292,570.79) ; 6481.39,2533.39 J33.4@6533.11,2533.39 v1(6574.25,2533.39)
  BOTTOM w15: 35.91,753.93 J20.B32@64.56,753.93 ; 35.91,990.15 J20.B26@64.56,990.15 ; 35.91,1147.63 J20.B22@64.56,1147.63 ; 35.91,1305.11 J20.B18@64.56,1305.11 ; 35.91,1383.85 J20.B16@64.56,1383.85 ; 35.91,1935.04 J20.B4@64.56,1935.04 ; 64.56,725.28 J20.B32@64.56,753.93 ; 64.56,782.59 J20.B32@64.56,753.93 ; 64.56,961.5 J20.B26@64.56,990.15 ; 64.56,1018.81 J20.B26@64.56,990.15 ; 64.56,1118.98 J20.B22@64.56,1147.63 ; 64.56,1176.29 J20.B22@64.56,1147.63 ; 64.56,1276.46 J20.B18@64.56,1305.11 ; 64.56,1333.77 J20.B18@64.56,1305.11 ; 64.56,1355.2 J20.B16@64.56,1383.85 ; 64.56,1412.51 J20.B16@64.56,1383.85 ; 64.56,1906.38 J20.B4@64.56,1935.04 ; 64.56,1963.69 J20.B4@64.56,1935.04 ; v1(105.3,3079.67) 105.52,3079.45 J15.31@169.61,3079.45 ; 213.07,793.3 J20.A31@241.73,793.3 ; 213.07,950.78 J20.A27@241.73,950.78 ; 213.07,1108.26 J20.A23@241.73,1108.26 ; 241.73,764.65 J20.A31@241.73,793.3 ; 241.73,821.96 J20.A31@241.73,793.3 ; 241.73,922.13 J20.A27@241.73,950.78 ; 241.73,979.44 J20.A27@241.73,950.78 ; 241.73,1079.61 J20.A23@241.73,1108.26 ; 241.73,1136.92 J20.A23@241.73,1108.26 ; 270.38,793.3 J20.A31@241.73,793.3 ; 270.38,950.78 J20.A27@241.73,950.78 ; 270.38,1108.26 J20.A23@241.73,1108.26 ; 277.53,178.81 SW4.1@312.09,178.81 ; 291.81,911.41 J20.A28@320.47,911.41 ; 291.81,1068.89 J20.A24@320.47,1068.89 ; 291.81,1226.37 J20.A20@320.47,1226.37 ; 312.09,144.25 SW4.1@312.09,178.81 ; 312.09,213.38 SW4.1@312.09,178.81 ; 320.47,882.76 J20.A28@320.47,911.41 ; 320.47,940.07 J20.A28@320.47,911.41 ; 320.47,1040.24 J20.A24@320.47,1068.89 ; 320.47,1097.55 J20.A24@320.47,1068.89 ; 320.47,1197.72 J20.A20@320.47,1226.37 ; 338.55,102.04 SW4.3@373.11,102.04 ; 346.65,178.81 SW4.1@312.09,178.81 ; 349.12,911.41 J20.A28@320.47,911.41 ; 349.12,1068.89 J20.A24@320.47,1068.89 ; 349.12,1226.37 J20.A20@320.47,1226.37 ; 373.11,67.48 SW4.3@373.11,102.04 ; 373.11,136.6 SW4.3@373.11,102.04 ; 407.67,102.04 SW4.3@373.11,102.04 ; 447.72,3412.17 J5.2@476.37,3412.17 ; 476.37,3353.97 J5.2@476.37,3412.17 ; 476.37,3470.37 J5.2@476.37,3412.17 ; 505.02,3412.17 J5.2@476.37,3412.17 ; 1152.7,532.79 SS7.1@1262.06,532.79 1262.06,642.15 ; 2474.17,159.06 J38.2@2509.72,159.06 ; 2509.72,123.51 J38.2@2509.72,159.06 ; 2509.72,194.6 J38.2@2509.72,159.06 ; 2545.27,159.06 J38.2@2509.72,159.06 ; 2574.17,159.06 J38.3@2609.72,159.06 ; 2609.72,123.51 J38.3@2609.72,159.06 ; 2609.72,194.6 J38.3@2609.72,159.06 ; 2645.27,159.06 J38.3@2609.72,159.06 ; 2867.52,127.95 J39.S1@2915.86,127.95 ; 2915.86,79.61 J39.S1@2915.86,127.95 ; 2915.86,176.29 J39.S1@2915.86,127.95 ; 2964.2,127.95 J39.S1@2915.86,127.95 ; 2992.32,108.27 J39.7@3020.98,108.27 ; 3020.98,79.61 J39.7@3020.98,108.27 ; 3020.98,136.92 J39.7@3020.98,108.27 ; 3049.64,108.27 J39.7@3020.98,108.27 ; 3142.32,108.27 J39.4@3170.98,108.27 ; 3170.98,79.61 J39.4@3170.98,108.27 ; 3170.98,136.92 J39.4@3170.98,108.27 ; 3199.64,108.27 J39.4@3170.98,108.27 ; 3292.32,108.27 J39.1@3320.98,108.27 ; 3320.98,79.61 J39.1@3320.98,108.27 ; 3320.98,136.92 J39.1@3320.98,108.27 ; 3349.64,108.27 J39.1@3320.98,108.27 ; 3377.76,127.95 J39.S2@3426.1,127.95 ; 3426.1,79.61 J39.S2@3426.1,127.95 ; 3426.1,176.29 J39.S2@3426.1,127.95 ; 3474.44,127.95 J39.S2@3426.1,127.95 ; 3751.13,532.79 SS8.1@3860.49,532.79 ; 3860.49,423.43 SS8.1@3860.49,532.79 ; 3860.49,642.15 SS8.1@3860.49,532.79 ; 3969.85,532.79 SS8.1@3860.49,532.79 ; C162.2@4629.68,1450 4659.37,1450 v1(4660,1449.37) ; 6230.88,136.22 SS11.1@6340.24,136.22 6340.24,245.58 ; 6701.27,374.72 J21.11@6749.61,374.72 ; 6749.61,348.04 J21.11@6749.61,374.72 ; 6749.61,401.41 J21.11@6749.61,374.72
  BOTTOM w20: v1(169.61,2245) J15.32@169.61,2339.3 ; v1(422.74,30.68) v1(572.74,30.68) v1(722.74,30.68) v1(872.74,30.68) v1(1022.74,30.68) v1(1172.73,30.68) v1(1322.73,30.68) v1(1472.73,30.68) v1(1622.73,30.68) v1(1772.73,30.68) v1(1922.73,30.68) v1(2072.74,30.68) v1(2222.74,30.68) v1(2372.74,30.68) v1(2522.74,30.68) v1(2672.74,30.68) v1(2822.74,30.68) v1(2972.74,30.68) v1(3122.74,30.68) ; v1(3272.74,30.68) v1(3422.74,30.68) v1(3572.74,30.68) v1(3722.74,30.68) ; J13.77@4821.93,2510.26 4821.93,2598.3 4843.26,2619.63 v1(4901.58,2619.63) ; v1(5633.86,2620.37) 5636.89,2617.34 J13.76@5636.89,2510.26 ; J21.9@6277.16,374.72 v1(6389.35,374.72) ; J21.8@6277.16,886.54 v1(6337,886.54) ; J37.26@6639.49,1037.95 6639.49,1112.88 ; 6639.49,1541.88 J37.25@6639.49,1624.57 J35.26@6639.49,1722.68 ; 6639.49,2236.86 J35.25@6639.49,2309.29 J33.26@6639.49,2407.4 ; v1(6639.49,2944.86) J33.25@6639.49,2994.01
  BOTTOM w30: R71.2@2030,3409.37 2034.96,3404.41 C57.2@2115,3404.41 2115,3610.87 R66.2@2106.5,3619.37 2106.5,3685.5 ; 2781.5,3666.5 R39.2@2781.5,3479.37 ; 2843.5,3664.5 R40.2@2843.5,3479.37 ; R39.2@2781.5,3479.37 2781.5,3435.87 R42.2@2760,3414.37 2764.96,3409.41 C36.2@2850,3409.41 2843.5,3415.91 R40.2@2843.5,3479.37 ; R39.2@2781.5,3479.37 R40.2@2843.5,3479.37
  other v1: 272.74,70.06 4312,137 3835,218 4187,219 4255,220 4521,220 4830,235 4396,254 4690,257 2606.43,260.11 2701.57,260.11 5447,305 5546,305 5585.37,305 5624.74,305 5340,307 5291,308 3150,315 6780.34,319.18 4354.37,320 4393.74,320 6582,322.19 5546,357 5585.37,357 5624.74,357 6582,361.56 4436.26,365 4475.63,365 4515,365 6582,400.93 5541,425 6582,440.3 5293.15,448.05 5332.52,448.05 5371.89,448.05 5450.62,448.05 354.05,450 1086,460.63 1125.37,460.63 6780.34,469.18 6582,479.67 774,500 813.37,500 852.74,500 1086,500 1125.37,500 6582,519.04 813.37,539.37 852.74,539.37 166.46,551.46 6582,558.41 1084,563.63 1123.37,563.63 774,578.74 813.37,578.74 852.74,578.74 3547,586 3603,586 6582,597.78 1084,603 1123.37,603 774,618.11 813.37,618.11 852.74,618.11 6780.34,619.18 6582,637.15 774,657.48 813.37,657.48 852.74,657.48 6582,676.52 574.5,709.39 605.99,709.39 637.48,709.39 6582,715.89 4957,717 4636,724 574.5,740.88 605.99,740.88 6582,755.26 6780.34,769.18 574.5,772.38 605.99,772.38 2639,780 6582,794.63 605.99,803.87 1779.71,814.63 1819.09,814.63 1858.45,814.63 1897.83,814.63 2858.85,826 6582,834 446.5,834.76 525.24,834.76 1819.09,854 1858.45,854 1897.83,854 2698,857 2741,858 2787,858 1181.26,910.37 1220.63,910.37 1260,910.37 1299.37,910.37 2743,944 2697,945 1181.26,949.74 1220.63,949.74 1260,949.74 1299.37,949.74 640.79,976.53 2813,978 1181.26,989.11 1220.63,989.11 1260,989.11 1299.37,989.11 1708,989 2873,1001 4813.21,1007.21 4852.58,1007.21 4891.95,1007.21 4931.32,1007.21 640.79,1008.02 680.16,1008.02 2767,1011 445.63,1012.6 2676,1021 1181.26,1028.48 1220.63,1028.48 1260,1028.48 1299.37,1028.48 1708,1028.37 445.63,1051.97 485,1051.97 524.37,1051.97 563.74,1051.97 1181.26,1067.85 1220.63,1067.85 1260,1067.85 1299.37,1067.85 1708,1067.74 6780.34,1069.18 4931.32,1085.95 445.63,1091.34 563.74,1091.34 603.11,1091.34 2634,1094 5008,1099 2242,1108 1906,1112 2762,1121 6618.62,1124.57 5421.89,1130 5461.26,1130 5500.63,1130 2860,1136 3057,1140 2944,1141 6657.99,1144.25 6618.62,1163.94 4931.32,1164.69 5421.89,1169.37 5461.26,1169.37 5500.63,1169.37 1045.63,1173.78 1124.37,1173.78 6657.99,1183.62 2995,1185 2792,1200 2944,1201 6382,1203 4813.21,1204.06 4852.58,1204.06 4891.95,1204.06 4931.32,1204.06 5049.43,1204.06 1045.63,1213.15 1085,1213.15 1124.37,1213.15 6780.34,1219.18 6618.62,1222.99 6657.99,1222.99 524.37,1239.37 568.74,1239.37 603.11,1239.37 4970.69,1243.43 5010.06,1243.43 5049.43,1243.43 701.89,1245.32 3047,1246 2792,1250 1163.74,1252.52 6382,1260 6579.25,1262.36 6618.62,1262.36 6657.99,1262.36 4532,1285.32 1163.74,1291.89 6579.25,1301.73 6618.62,1301.73 6657.99,1301.73 5415,1315 5454.37,1315 5493.74,1315 5533.11,1315 2927,1320 4020.32,1321.26 4059.69,1321.26 4099.06,1321.26 3784,1333 6579.25,1341.1 6618.62,1341.1 6657.99,1341.1 3541,1348 3585,1348 2058,1349 1744,1350 2445,1351 3253.55,1356.63 4099.06,1360.63 1503,1364 6780.34,1369.18 1045.63,1370.63 1085,1370.63 1124.37,1370.63 1359,1376 6579.25,1380.47 6618.62,1380.47 6657.99,1380.47 534.49,1395 573.86,1395 4099.06,1400 6618.62,1419.84 6657.99,1419.84 3594,1424 4560.63,1424.37 5068,1424 1744,1426 2061,1428 1505,1429 1868,1429 2623.63,1430.37 3809,1433 534.49,1434.37 573.86,1434.37 3979,1438 6618.62,1459.21 6657.99,1459.21 2445,1475 534.49,1476.74 573.86,1476.74 2726,1480 2781.11,1479.74 2820.48,1479.74 2859.85,1479.74 2977.96,1479.74 3056.7,1479.74 3978,1480.37 1574,1485 5211,1487 4744.84,1494.84 4803.58,1494.84 6618.62,1498.58 6657.99,1498.58 5449.26,1501.26 5488.63,1501.26 5528,1501.26 3978,1518 6780.34,1519.18 1045.63,1527.89 1124.37,1527.89 4803.58,1534.21 6122,1538 6161.37,1538 6200.74,1538 6618.62,1537.95 6657.99,1537.95 5528,1540.63 3978,1560.37 1045.63,1562.26 1124.37,1562.26 5528,1580 3543,1583 3582.37,1583 6380.63,1589.99 455.75,1590.63 731.34,1590.63 4089.09,1591.58 4128.47,1591.58 4167.84,1591.58 3701,1593 3979,1595 1045.63,1601.63 1085,1601.63 1124.37,1601.63 4803.58,1612.95 1604,1624.63 1562,1626.63 455.75,1630 613.23,1630 652.6,1630 691.97,1630 731.34,1630 810.08,1630 1525,1635.63 6225.59,1641.89 6264.96,1641.89 6499.37,1641.89 3180,1645 3979.69,1647 1745,1663 1604,1664 1822.63,1663.74 1562,1666 455.75,1669.37 495.12,1669.37 534.49,1669.37 573.86,1669.37 770.71,1669.37 810.08,1669.37 6780.34,1669.18 1525,1675 4778.11,1679.37 6068.11,1681.26 6107.48,1681.26 6225.59,1681.26 6264.96,1681.26 6304.33,1681.26 6499.37,1681.26 5785,1691 3220,1695 2062,1708 2437.78,1709 2477.15,1709 2516.52,1709 2555.89,1709 2595.26,1709 2634.63,1709 2674,1709 1743,1719 1525,1720 1600,1720 1890,1721 6068.11,1720.63 6107.48,1720.63 6304.33,1720.63 6499.37,1720.63 3250,1745 6068.11,1760 6107.48,1760 6304.33,1760 6380.63,1760 1525,1770 1600,1770 1889,1772 1124.37,1788.26 1163.74,1788.26 6380.63,1799.37 4437,1814 808.11,1815.63 1744,1817 6780.34,1819.18 1525,1820 1600,1820 1888,1820 1045.63,1827.63 1085,1827.63 1163.74,1827.63 6447.6,1848.66 6579.25,1848.66 6618.62,1848.66 4210,1850 690,1855 729.37,1855 768.74,1855 808.11,1855 847.48,1855 1163.74,1867 1520,1870 1600,1870 6089.6,1884.37 6469,1893 455.75,1894.37 495.12,1894.37 534.49,1894.37 573.86,1894.37 729.37,1894.37 768.74,1894.37 808.11,1894.37 847.48,1894.37 6618.62,1907.72 5910.63,1917.48 5950,1917.48 1520,1920 6089.6,1923.74 6128.97,1923.74 1745,1929 2415,1930 2460,1930 534.49,1933.74 573.86,1933.74 6579.25,1947.09 6618.62,1947.09 1600,1950 6343,1955 5910.63,1956.85 5950,1956.85 6089.6,1963.11 6780.34,1969.18 1995,1973 5025.63,1976.62 6579.25,1986.46 6618.62,1986.46 5950,1996.22 1521,1999 1600,1999.25 6089.6,2002.48 2365,2005 2412,2005 5511,2008 1149.6,2013.94 5705,2020.32 5744.37,2020.32 6579.25,2025.83 6618.62,2025.83 1358,2040 1522,2043 2665,2045 2460,2048 2515,2048 4538,2049 1070.86,2053.31 1110.23,2053.31 1149.6,2053.31 1216,2054 4834.05,2059.69 4873.42,2059.69 4912.79,2059.69 5744.37,2059.69 460.31,2063.31 677.16,2063.31 716.53,2063.31 6579.25,2065.2 6618.62,2065.2 2319,2078 1523,2088.75 1358,2090 460.31,2102.68 519.68,2102.68 559.05,2102.68 598.42,2102.68 637.79,2102.68 677.16,2102.68 716.53,2102.68 750.9,2102.68 795.27,2102.68 834.64,2102.68 874.01,2102.68 913.38,2102.68 952.75,2102.68 992.12,2102.68 1031.49,2102.68 1070.86,2102.68 1110.23,2102.68 1149.6,2102.68 6618.62,2104.57 6342,2115 6780.34,2119.18 1599,2132 6618.62,2143.94 2540,2158 420.94,2181.42 1149.6,2181.42 2256,2183 6618.62,2183.31 2510,2185 420.94,2220.79 1149.6,2220.79 622.52,2222.52 661.89,2222.52 740.63,2222.52 6066.11,2222.89 6105.48,2222.89 6144.85,2222.89 6618.62,2222.68 992.37,2233 1031.74,2233 208.98,2245 6066.11,2262.26 6105.48,2262.26 6144.85,2262.26 6780.34,2269.18 6385.63,2279.37 1622.6,2282.7 208,2286 6066.11,2301.63 6105.48,2301.63 6144.85,2301.63 5729,2310 6499.37,2331.27 6066.11,2341 6105.48,2341 6144.85,2341 6499.37,2370.64 6538.74,2370.64 6499.37,2410.01 6574.25,2415.28 6780.34,2419.18 6142,2431 5891,2433 6574.25,2454.64 4737,2467 4441,2476 2597.62,2480.63 6341.26,2488.75 6380.63,2488.75 635.63,2490.43 6274,2498 195.63,2502.69 635.63,2529.8 3908,2532 5918,2533.74 5957.37,2533.74 6320,2539.37 596.26,2569.17 635.63,2569.17 695,2569.17 769.37,2569.17 6780.34,2569.18 5918,2573.11 6252,2580 6389,2584 6320,2589.37 6660,2594 4297,2602 596.26,2608.54 635.63,2608.54 4488,2611 1729.13,2613.46 1816.48,2613.46 4439.37,2613 4236,2614 6079,2618 6146,2618 3294,2635 3337,2635 3645,2636 3784,2636 3486,2641 6265,2644 635.63,2647.91 2634.63,2652.2 1480,2652.83 1519.37,2652.83 1729.13,2652.83 1816.48,2652.83 1035,2655.63 1074.37,2655.63 800,2670 6642,2680 635.63,2687.28 3380,2688 1365,2692.2 1480,2692.2 1519.37,2692.2 1729.13,2692.2 1816.48,2692.2 1280.98,2693.74 995.63,2695 1074.37,2695 4167,2696 438.11,2719.43 477.48,2719.43 6780.34,2719.18 1480,2731.57 1519.37,2731.57 1729.13,2731.57 1816.48,2731.57 1280.98,2733.11 1365,2733.11 2419.05,2749.68 2458.42,2749.68 3130.37,2749.68 3169.74,2749.68 6617.99,2749.92 2010.22,2750.63 2049.59,2750.63 2088.96,2750.63 2734.63,2750.63 2774,2750.63 2813.37,2750.63 4479,2754 398.74,2758.8 438.11,2758.8 477.48,2758.8 105,2765 2330.28,2765.35 6220,2770 1280.98,2772.48 1365,2772.48 6684,2780 2458.42,2789.05 3169.74,2789.05 2010.22,2790 2049.59,2790 2088.96,2790 2734.63,2790 2774,2790 2813.37,2790 6304,2796 6349,2796 5780.49,2796.71 5819.86,2796.71 398.74,2798.17 634.96,2798.17 1729,2811 1280.98,2811.85 6065,2812.21 6104.37,2812.21 4315,2824 6442,2825 2458.42,2828.42 3169.74,2828.42 2010.22,2829.37 2049.59,2829.37 2088.96,2829.37 2734.63,2829.37 2774,2829.37 2813.37,2829.37 95,2835 6651,2835 398.74,2837.54 634.96,2837.54 674.33,2837.54 1280.98,2851.22 1365,2851.22 2458.42,2867.79 3169.74,2867.79 5523.51,2867.88 5555,2867.88 5586.49,2867.88 6780.34,2869.18 5888.6,2875.45 398.74,2876.91 438.11,2876.91 634.96,2876.91 674.33,2876.91 5523.51,2899.37 5555,2899.37 5586.49,2899.37 95,2900 2458.42,2907.16 3780,2914.37 5888.6,2914.82 6389.3,2925.36 4829.37,2926.87 5049.37,2926.87 1365,2929.96 6259.68,2930 5523.51,2930.86 5555,2930.86 5586.49,2930.86 2541,2934 6578.62,2946.77 95,2950 5888.6,2954.19 6389.3,2964.73 1365,2969.33 6259.68,2969.37 1711,2989 1750.37,2989 5701.75,2993.56 5741.12,2993.56 5780.49,2993.56 5819.86,2993.56 5859.23,2993.56 2519,3001 2409.24,3002.17 5637,3002.37 5473,3003 1017,3011 1278,3015 6780.34,3019.18 6264.05,3040 1630,3042.48 6527,3044 5916,3056 5378,3057 5310,3058 5636,3059.37 5675.37,3059.37 5714.74,3059.37 5754.11,3059.37 5793.48,3059.37 6292,3060 1243,3075 1384,3075 381.09,3078.51 2464.68,3079.68 1100,3085 381.09,3110 420.46,3110 5622.1,3110.89 5661.47,3110.89 5700.84,3110.89 5740.21,3110.89 5779.58,3110.89 5818.95,3110.89 5344,3123 904.37,3125 1145,3130 1190,3130 1270,3130 1365,3130 1208,3154 2464.68,3158.42 6780.34,3169.18 3454,3171 1440,3180 1505,3180 6498,3199 1381.43,3205 1420.8,3205 1529.7,3205 1608.44,3205 6217,3205 6403,3208 6286,3209 6346,3210 1240,3216 1279.37,3216 1318.74,3216 3872,3239.37 3455,3243.37 4305,3244.37 1074,3252 1651,3269 1597,3270 1353,3274 1490,3274 676.05,3275.32 1048,3276 1144,3276 996,3278 5995.75,3297.4 6035.12,3297.4 6074.49,3297.4 6113.86,3297.4 6153.23,3297.4 6192.6,3297.4 4305,3300.12 3455,3309.37 3871,3311.37 552,3314.37 636.68,3314.69 676.05,3314.69 6780.34,3319.18 5995.75,3336.77 6035.12,3336.77 6074.49,3336.77 6153.23,3336.77 6192.6,3336.77 1476,3345.37 263,3354 552,3353.74 3905,3354.37 3455,3374.37 4288,3373.8 263,3393.37 263,3432.74 4288,3464.37 874.45,3479.39 4710.95,3497.05 4825.95,3497.05 4865.32,3497.05 4904.69,3497.05 1159.44,3501.65 1615,3503 6780.34,3508.55 4710.95,3536.42 5905,3565 4710.95,3575.79 5594.37,3578.37 5633.74,3578.37 553,3617.37 615.98,3617.37 892,3617.37 1133,3617.77 1165,3618 1670,3619.37 3162.63,3629 921.26,3629.68 4403.54,3630.73 4442.91,3630.73 553,3656.74 615.98,3656.74 4821.26,3659.37 4860.63,3659.37 4939.37,3659.37 1011.8,3660.86 4403.54,3670.1 4292.91,3709.47 4332.28,3709.47 4403.54,3709.47 1405,3712.88 1436.49,3712.88 1436.49,3744.37
  other v2: 1484.35,270.1 1484.35,309.47 2142,324 4967,327 5006.37,327 3569,387 3600,387 2231.2,387.89 2412.3,387.89 3469.1,387.89 2614,389 2555,391 2759,391 2515,395 2861,420 2977,420 1717.39,421.68 1748.88,421.68 2009,427 1602.46,427.58 1653.44,500.42 1719.39,500.42 1748.88,500.42 2507,503 1563.09,506.32 1602.46,506.32 2718.11,510.36 2555,519 2600,519 1748.88,531.91 1563.09,545.69 1602.46,545.69 2601,578 1563.09,585.06 1602.46,585.06 2511,610 2558,613 2443.8,654.06 2620,662 2512,666 2552,666 1971.36,679.18 2002.86,679.18 2443.8,693.43 2575,708 2891,731 2834,732 2637,824 2635,858 6328,1329 6329,1370 6401,1370 6401,1410 6401,1450 3349,2348 3072.45,2359 2930,2390 1656.4,2392 1656.4,2431.37 1600,2482 2136,2488
HDMI0_5V: C141.1 D26.1 D32.2 J16.18 R152.1 R155.1 | length 885.8
  TOP w10: R152.1@3250.32,2735 3250.32,2779.06 v1(3255.63,2784.37)
  ART04 w10: J16.18@3397.09,3056.98 3397.09,2950 3377.09,2930 3292.63,2930 3272.63,2910 3272.63,2801.37 v1(3255.63,2784.37) 3255.63,2609.37 3280,2585 3380,2585 3400,2565 v1(3400,2520)
  ART04 w15: J16.18@3374.34,3056.98 J16.18@3397.09,3056.98 J16.18@3419.84,3056.98
  BOTTOM w10: v1(3400,2520) R155.1@3400,2545.32
  other v1: 3422.52,3590 3461.89,3590 3422.52,3629.37 3461.89,3629.37
HDMI0_EARC+: C139.2 D30.2 J16.14 | length 921.7
  TOP w4.5: J16.14@3397.09,3148.01 3413.09,3132 cw(c3397.18,3116.09) 3419.68,3116.09 3419.68,3056 cw(c3397.18,3056.01) 3413.09,3040.09 3396.59,3023.59 ccw(c3412.5,3007.68) 3390,3007.68 3390,2987 cw(c3371.5,2987) 3371.5,2968.5 3320,2968.5 ccw(c3320,2956) 3307.5,2956 3307.5,2919.22 cw(c3286.75,2919.22) 3286.75,2898.47 3237.75,2898.47 ccw(c3237.75,2887.22) 3237.75,2875.97 3286.75,2875.97 cw(c3286.75,2855.22) 3307.5,2855.22 3307.5,2817.5 ccw(c3316.5,2817.5) 3316.5,2808.5 3326,2808.5 ccw(c3326,2817.5) 3335,2817.5 3335,2920 cw(c3354.5,2920) 3354.5,2939.5 3385.75,2939.5 cw(c3385.75,2921) 3404.25,2921 3404.25,2854.19 ccw(c3414.98,2854.19) 3407.39,2846.6 3408.03,2845.96 cw(c3400.44,2838.38) 3411.17,2838.38 D30.2@3411.17,2830 3407.4,2826.23 ccw(c3414.96,2818.68) 3404.27,2818.68 3404.27,2813.13 ccw(c3412.38,2813.13) 3406.65,2807.4 C139.2@3420,2794.05
HDMI0_EARC-: C140.2 D27.2 J16.19 R159.2 | length 918.7
  TOP w4.5: J16.19@3357.72,3034.23 3357.72,3043.28 ccw(c3349,3043.28) 3349,3052 3324,3052 ccw(c3324,3043) 3315,3043 3315,3015.37 ccw(c3324,3015.37) 3324,3006.37 3375,3006.37 cw(c3375,3000.87) 3380.5,3000.87 3380.5,2987 cw(c3371.5,2987) 3371.5,2978 3320,2978 ccw(c3320,2956) 3298,2956 3298,2919.22 cw(c3286.75,2919.22) 3286.75,2907.97 3237.75,2907.97 ccw(c3237.75,2887.22) 3237.75,2866.47 3286.75,2866.47 cw(c3286.75,2855.22) 3298,2855.22 3298,2817.5 ccw(c3316.5,2817.5) 3316.5,2799 3326,2799 ccw(c3326,2817.5) 3344.5,2817.5 3344.5,2920 cw(c3354.5,2920) 3354.5,2930 3385.75,2930 cw(c3385.75,2921) 3394.75,2921 3394.75,2854.19 cw(c3384.02,2854.19) 3391.61,2846.6 3390.97,2845.96 ccw(c3398.56,2838.38) 3387.83,2838.38 D27.2@3387.83,2830 3391.62,2826.21 cw(c3384.01,2818.6) 3394.77,2818.6 3394.77,2812.18 cw(c3386.67,2812.18) 3392.4,2806.45 v1(3380,2794.05)
HDMI0_TX_ON: J4.89 R169.1 | length 911.2
  TOP w6: v2(3355.92,2225.14) 3371.66,2240.89 J4.89@3371.66,2286.88
  BOTTOM w6: v2(3355.92,2225.14) 3372,2241.23 3372,2250.93 3371.92,2251.01 3371.92,2265.28 3372,2265.36 3372,2271 3384,2283 3460,2283 3512,2231 4067,2231 4080.32,2244.32 R169.1@4080.32,2294.37
HDMI1_5V: C153.1 D33.1 D39.2 J17.18 R173.1 R176.1 | length 1292
  ART04 w10: J17.18@3822.28,3056.98 3822.28,2956.09 3863,2915.37 3863,2789.37 3883,2769.37 4120,2769.37 4146,2743.37 4146,2548 4166,2528 v1(4280,2528)
  BOTTOM w10: R173.1@4210,2549.69 4231.69,2528 v1(4280,2528) 4311.63,2496.37 4502,2496.37 4515,2509.37 R176.1@4515,2544.69
  other v1: 3758.78,3591.26 3798.15,3591.26 3758.78,3630.63 3798.15,3630.63
HDMI1_EARC+: C151.2 D37.2 J17.14 | length 556.5
  TOP w4.5: J17.14@3822.28,3148.01 3843.77,3126.52 cw(c3814.26,3097) 3856,3097 3856,3063.8 cw(c3808.2,3063.8) 3842,3030 3828.49,3016.49 ccw(c3848.97,2996) 3820,2996 3820,2991.47 cw(c3801.5,2991.47) 3801.5,2972.97 3793.5,2972.97 ccw(c3793.5,2963.97) 3784.5,2963.97 3784.5,2963.22 ccw(c3792.75,2963.22) 3792.75,2954.97 3802.93,2954.97 cw(c3802.93,2937.9) 3820,2937.9 3820,2930.34 ccw(c3829.48,2930.34) 3829.48,2920.85 3891.5,2920.85 cw(c3891.5,2902.35) 3891.5,2883.85 3864.75,2883.85 ccw(c3864.75,2874.85) 3855.75,2874.85 3855.75,2852.6 ccw(c3863.85,2852.6) 3858.12,2846.87 3859.28,2845.71 cw(c3852.3,2838.73) 3862.17,2838.73 D37.2@3862.17,2830 3858.4,2826.23 ccw(c3865.96,2818.68) 3855.27,2818.68 3855.27,2812.13 ccw(c3863.38,2812.13) 3857.65,2806.4 C151.2@3870,2794.05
